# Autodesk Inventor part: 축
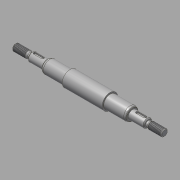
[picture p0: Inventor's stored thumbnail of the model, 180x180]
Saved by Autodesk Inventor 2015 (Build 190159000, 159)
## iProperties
Created: 2015-11
Part Number: 축
Material: 강철, 연강
Document SubType Name: Modeling
Designer: mduedu
Density: 1 g/cm^3
Appearance: 강철
Author: mduedu
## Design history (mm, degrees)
sketch "스케치1"
  geometry: L1 (-86, 0)-(86, 0); L2 (-86, 0)-(-86, 4); L3 (-86, 4)-(-70.732, 4); L4 (-70.732, 4)-(-69, 3); L5 (-69, 3)-(-67, 3); L6 (-67, 3)-(-67, 5); L7 (-67, 5)-(-49, 5); L8 (-49, 5)-(-49, 6.55); L9 (-47.355, 7.5)-(-23, 7.5); L10 (-23, 7.5)-(-23, 9); L11 (0, 0)-(0, 9); L12 (86, 4)-(70.732, 4); L13 (70.732, 4)-(69, 3); L14 (69, 3)-(67, 3); L15 (67, 3)-(67, 5); L16 (67, 5)-(49, 5); L17 (23, 7.5)-(23, 9); L18 (86, 0)-(86, 4); L19 (-23, 9)-(23, 9); L20 (-49, 6.55)-(-47.355, 7.5); L21 (47.355, 7.5)-(23, 7.5); L22 (49, 6.55)-(47.355, 7.5); L23 (49, 5)-(49, 6.55); 1 further point
  constraints: 46 end point, 10 symmetric about line, 6 perpendicular, 5 parallel, 2 midpoint, 1 coincident, 1 horizontal
  dimensions: "d0" = 172 distance of L1.start L1.end (derived); "d1" = 8 diameter of L3 L1; "d2" = 30 deg angle of L4 L5; "d3" = 6 diameter of L5 L1; "d4" = 10 diameter of L7 L1; "d5" = 15 diameter of L9 L1; "d6" = 18 diameter of L19 L1; "d8" = 18 distance of L6.end L7.end; "d9" = 46 distance of L10.end L17.end; "d10" = 2 distance of L4.end L5.end; "d11" = 17 distance from line of L4.end L2; "d16" = 13.1 diameter of L8.end L1; "d17" = 30 deg angle of L20 L9; "d18" = 26 distance between parallel lines of L10 L8
revolve "회전1" sketch "스케치1" stored, may be unused: angle "d12" = 90 deg
chamfer "모따기1" distance "d13" = 1; stored, may be unused: second distance "d14" = 2, angle "d15" = 45 deg
fillet "모깎기1" dims "d19" = 4, "d20" = 0.5
node "작업 평면1"
sketch "스케치2" dims "d23" = 12
  geometry: L1 (-5.5, 1.5)-(3.5, 1.5); L2 (3.5, 1.5)-(3.5, -1.5); L3 (3.5, -1.5)-(-5.5, -1.5); L4 (-5.5, -1.5)-(-5.5, 1.5); L5 (-9, -4)-(-9, 4) reference; 3 further points
  constraints: 8 end point, 2 midpoint, 2 parallel, 2 vertical alignment, 1 horizontal, 1 perpendicular, 4 other
  dimensions: "d21" = 3 distance between parallel lines of L3 L1; "d24" = 2 dimension on L5
extrude "돌출1" cut sketch "스케치2" distance "d25" = 1.8; taper "d26" = 0 deg
feature "스레드1" dims "d27" = 10, "d28" = 0
feature "스레드2" dims "d29" = 10, "d30" = 0
chamfer "모따기2" distance "d31" = 1; stored, may be unused: second distance "d32" = 2, angle "d33" = 45 deg
fillet "모깎기2" dims "d34" = 0.3
node "솔리드1"
mirror "대칭1"
